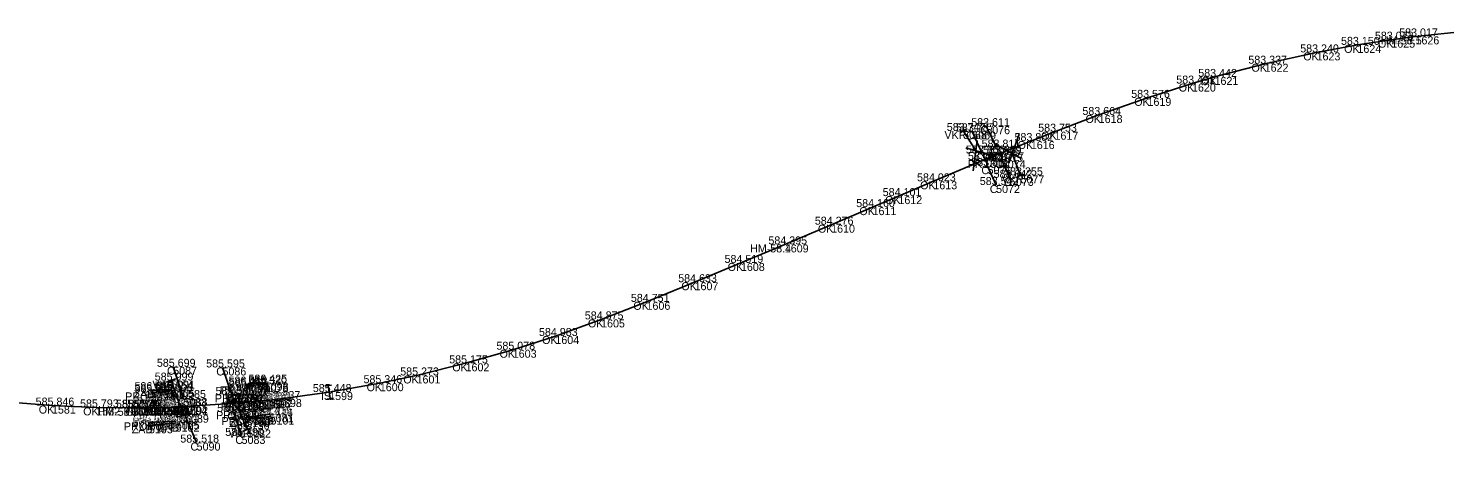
# Model space of a CAD drawing. Extents: x -631472 to -620808, y -1122356 to -1115125.
# Drawn here: x -623680.4 to -623468, y -1119636.8 to -1119573.4 of the extents above; entities that cross this region are included whole.
import ezdxf

# ---------------------------------------------------------------- set-up
doc = ezdxf.new("R2010")
doc.units = 0
for name, color, linetype in [('Vrstva 1', 7, 'Continuous'), ('Vrstva 17', 7, 'Continuous'), ('Vrstva 18', 7, 'Continuous'), ('Vrstva 3', 7, 'Continuous'), ('Vrstva 4', 7, 'Continuous'), ('Vrstva 51', 7, 'Continuous'), ('Vrstva 60', 7, 'Continuous'), ('Vrstva 61', 7, 'Continuous'), ('Vrstva 62', 7, 'Continuous')]:
    doc.layers.add(name, color=color, linetype=linetype)

msp = doc.modelspace()

# ---------------------------------------------------------------- linework, layer by layer
at = {"layer": 'Vrstva 1'}
msp.add_lwpolyline([(-623685.11, -1119629.35), (-623676.9, -1119629.99), (-623670.24, -1119630.26), (-623664.87, -1119630.32), (-623663.9, -1119630.31), (-623663.16, -1119630.3), (-623662.36, -1119630.29), (-623661.98, -1119630.29), (-623661.49, -1119630.28), (-623660.47, -1119630.26), (-623658.91, -1119630.21), (-623658.39, -1119630.19), (-623657.06, -1119630.14), (-623648.54, -1119629.57), (-623647.77, -1119629.5), (-623646.15, -1119629.35), (-623644.69, -1119629.2), (-623644.37, -1119629.16), (-623643, -1119629.01), (-623635.33, -1119627.96), (-623627.73, -1119626.63), (-623622.22, -1119625.47), (-623614.87, -1119623.65), (-623607.79, -1119621.61), (-623601.4, -1119619.55), (-623594.54, -1119617.06), (-623587.73, -1119614.43), (-623580.53, -1119611.48), (-623573.57, -1119608.59), (-623566.99, -1119605.81), (-623560.04, -1119602.85), (-623553.83, -1119600.21), (-623549.95, -1119598.56), (-623544.71, -1119596.34), (-623537.09, -1119593.14), (-623534.83, -1119592.21), (-623530.09, -1119590.3), (-623526.54, -1119588.9), (-623519.91, -1119586.39), (-623512.59, -1119583.82), (-623505.92, -1119581.68), (-623502.54, -1119580.68), (-623495.02, -1119578.7), (-623487.24, -1119577), (-623481.11, -1119575.87), (-623476.03, -1119575.09), (-623472.4, -1119574.6), (-623464.76, -1119573.83)], dxfattribs=at)
at = {"layer": 'Vrstva 17'}
for p, q in [((-623647.98, -1119626.84), (-623644.99, -1119626.55)), ((-623662.07, -1119627.68), (-623659.04, -1119627.58)), ((-623662.35, -1119632.95), (-623658.36, -1119632.7)), ((-623647.75, -1119632.01), (-623644.12, -1119631.64))]:
    msp.add_line(p, q, dxfattribs=at)
at = {"layer": 'Vrstva 18'}
for p, q in [((-623647.9, -1119627.1), (-623645.01, -1119626.8)), ((-623662.07, -1119628.02), (-623659.16, -1119627.88)), ((-623662.28, -1119632.5), (-623658.32, -1119632.37)), ((-623647.63, -1119631.71), (-623644.24, -1119631.28))]:
    msp.add_line(p, q, dxfattribs=at)
at = {"layer": 'Vrstva 3'}
for p, q in [((-623635.96, -1119627.04), (-623634.97, -1119626.91)), ((-623635.69, -1119629.02), (-623634.7, -1119628.89)), ((-623635.47, -1119626.97), (-623635.2, -1119628.95)), ((-623662.01, -1119629.29), (-623661.01, -1119629.27)), ((-623661.51, -1119629.28), (-623661.47, -1119631.28)), ((-623661.97, -1119631.29), (-623660.97, -1119631.27))]:
    msp.add_line(p, q, dxfattribs=at)
at = {"layer": 'Vrstva 4'}
for p, q in [((-623539.83, -1119588.52), (-623540.67, -1119589.06)), ((-623540.25, -1119588.79), (-623538.35, -1119591.73)), ((-623538.13, -1119590.22), (-623538.76, -1119594.79)), ((-623535.58, -1119590.68), (-623531.54, -1119592.9)), ((-623533.41, -1119593.6), (-623531.83, -1119589.27)), ((-623535.4, -1119592.63), (-623539.82, -1119591.31)), ((-623537.09, -1119593.14), (-623534.83, -1119592.21)), ((-623531.64, -1119595.45), (-623532.88, -1119592.17)), ((-623532.11, -1119595.62), (-623531.18, -1119595.27)), ((-623658.3, -1119625.98), (-623659.77, -1119626.5)), ((-623649.65, -1119629.38), (-623649.47, -1119628.92)), ((-623657.28, -1119630.57), (-623657.5, -1119631.01)), ((-623657.06, -1119630.14), (-623648.54, -1119629.57)), ((-623648.34, -1119633.89), (-623646.91, -1119633.29))]:
    msp.add_line(p, q, dxfattribs=at)
for points in [[(-623659.03, -1119626.24), (-623657.87, -1119629.52), (-623656.27, -1119631.08), (-623658.16, -1119631.75), (-623657.87, -1119629.52)], [(-623647.63, -1119633.59), (-623648.99, -1119630.39), (-623650.69, -1119628.94), (-623648.85, -1119628.15), (-623648.99, -1119630.39)]]:
    msp.add_lwpolyline(points, dxfattribs=at)
for centre in [(-623649.56, -1119629.15), (-623657.39, -1119630.79)]:
    msp.add_circle(centre, 0.248, dxfattribs=at)
at = {"layer": 'Vrstva 51'}
for p, q in [((-623535.22, -1119591.28), (-623536.78, -1119588.07)), ((-623537.38, -1119592.18), (-623538.88, -1119588.86)), ((-623535.3, -1119596.9), (-623536.57, -1119594.07)), ((-623533.23, -1119595.82), (-623534.45, -1119593.17)), ((-623657.15, -1119628.85), (-623658.72, -1119624.17)), ((-623649.91, -1119628.39), (-623651.33, -1119624.27)), ((-623648.46, -1119634.54), (-623649.67, -1119630.94)), ((-623655.2, -1119635.54), (-623656.95, -1119631.36))]:
    msp.add_line(p, q, dxfattribs=at)
at = {"layer": 'Vrstva 60'}
for p, q in [((-623476.03, -1119575.09), (-623476.03, -1119575.09)), ((-623472.4, -1119574.6), (-623472.4, -1119574.6)), ((-623487.24, -1119577), (-623487.24, -1119577)), ((-623481.11, -1119575.87), (-623481.11, -1119575.87)), ((-623495.02, -1119578.7), (-623495.02, -1119578.7)), ((-623505.92, -1119581.68), (-623505.92, -1119581.68)), ((-623502.54, -1119580.68), (-623502.54, -1119580.68)), ((-623512.59, -1119583.82), (-623512.59, -1119583.82)), ((-623519.91, -1119586.39), (-623519.91, -1119586.39)), ((-623530.09, -1119590.3), (-623530.09, -1119590.3)), ((-623526.54, -1119588.9), (-623526.54, -1119588.9)), ((-623534.83, -1119592.21), (-623534.83, -1119592.21)), ((-623537.09, -1119593.14), (-623537.09, -1119593.14)), ((-623544.71, -1119596.34), (-623544.71, -1119596.34)), ((-623549.95, -1119598.56), (-623549.95, -1119598.56)), ((-623553.83, -1119600.21), (-623553.83, -1119600.21)), ((-623560.04, -1119602.85), (-623560.04, -1119602.85)), ((-623566.99, -1119605.81), (-623566.99, -1119605.81)), ((-623573.57, -1119608.59), (-623573.57, -1119608.59)), ((-623580.53, -1119611.48), (-623580.53, -1119611.48)), ((-623587.73, -1119614.43), (-623587.73, -1119614.43)), ((-623594.54, -1119617.06), (-623594.54, -1119617.06)), ((-623601.4, -1119619.55), (-623601.4, -1119619.55)), ((-623607.79, -1119621.61), (-623607.79, -1119621.61)), ((-623614.87, -1119623.65), (-623614.87, -1119623.65)), ((-623627.73, -1119626.63), (-623627.73, -1119626.63)), ((-623622.22, -1119625.47), (-623622.22, -1119625.47)), ((-623635.33, -1119627.96), (-623635.33, -1119627.96)), ((-623676.9, -1119629.99), (-623676.9, -1119629.99)), ((-623670.24, -1119630.26), (-623670.24, -1119630.26)), ((-623664.87, -1119630.32), (-623664.87, -1119630.32)), ((-623663.9, -1119630.31), (-623663.9, -1119630.31)), ((-623663.16, -1119630.3), (-623663.16, -1119630.3)), ((-623662.36, -1119630.29), (-623662.36, -1119630.29)), ((-623661.98, -1119630.29), (-623661.98, -1119630.29)), ((-623661.49, -1119630.28), (-623661.49, -1119630.28)), ((-623660.47, -1119630.26), (-623660.47, -1119630.26)), ((-623658.91, -1119630.21), (-623658.91, -1119630.21)), ((-623658.39, -1119630.19), (-623658.39, -1119630.19)), ((-623657.06, -1119630.14), (-623657.06, -1119630.14)), ((-623648.54, -1119629.57), (-623648.54, -1119629.57)), ((-623647.77, -1119629.5), (-623647.77, -1119629.5)), ((-623646.15, -1119629.35), (-623646.15, -1119629.35)), ((-623644.69, -1119629.2), (-623644.69, -1119629.2)), ((-623644.37, -1119629.16), (-623644.37, -1119629.16)), ((-623643, -1119629.01), (-623643, -1119629.01))]:
    msp.add_line(p, q, dxfattribs=at)

# ---------------------------------------------------------------- texts
for s, p in [('1624', (-623481.11, -1119577.07)), ('1625', (-623476.03, -1119576.29)), ('1626', (-623472.4, -1119575.8)), ('1623', (-623487.24, -1119578.2)), ('1622', (-623495.02, -1119579.9)), ('1620', (-623505.92, -1119582.88)), ('1621', (-623502.54, -1119581.88)), ('1619', (-623512.59, -1119585.02)), ('1618', (-623519.91, -1119587.59)), ('5076', (-623536.78, -1119589.27)), ('5068', (-623540.25, -1119589.99)), ('5069', (-623538.88, -1119590.06)), ('1616', (-623530.09, -1119591.5)), ('1617', (-623526.54, -1119590.1)), ('5070', (-623537.38, -1119593.38)), ('5075', (-623535.22, -1119592.48)), ('1615', (-623534.83, -1119593.41)), ('1614', (-623537.09, -1119594.34)), ('5071', (-623536.57, -1119595.27)), ('5074', (-623534.45, -1119594.37)), ('1613', (-623544.71, -1119597.54)), ('5072', (-623535.3, -1119598.1)), ('5073', (-623533.23, -1119597.02)), ('5077', (-623531.64, -1119596.65)), ('1612', (-623549.95, -1119599.76)), ('1611', (-623553.83, -1119601.41)), ('1610', (-623560.04, -1119604.05)), ('1609', (-623566.99, -1119607.01)), ('1608', (-623573.57, -1119609.79)), ('1607', (-623580.53, -1119612.68)), ('1606', (-623587.73, -1119615.62)), ('1605', (-623594.54, -1119618.26)), ('1604', (-623601.4, -1119620.75)), ('1603', (-623607.79, -1119622.81)), ('5087', (-623658.72, -1119625.37)), ('5086', (-623651.33, -1119625.47)), ('1602', (-623614.87, -1119624.85)), ('5091', (-623659.03, -1119627.44)), ('5099', (-623647.98, -1119628.04)), ('5078', (-623645.01, -1119628.01)), ('5098', (-623644.99, -1119627.75)), ('1600', (-623627.73, -1119627.83)), ('1601', (-623622.22, -1119626.67)), ('5104', (-623662.07, -1119628.88)), ('5093', (-623662.07, -1119629.22)), ('5092', (-623659.16, -1119629.08)), ('5105', (-623659.04, -1119628.78)), ('5088', (-623657.15, -1119630.05)), ('5085', (-623649.91, -1119629.59)), ('5097', (-623648.62, -1119629.51)), ('5079', (-623647.9, -1119628.3)), ('1599', (-623635.33, -1119629.16)), ('1581', (-623676.9, -1119631.19)), ('1582', (-623670.24, -1119631.46)), ('1583', (-623664.87, -1119631.52)), ('1584', (-623663.9, -1119631.51)), ('1585', (-623663.16, -1119631.5)), ('1586', (-623662.36, -1119631.49)), ('1587', (-623661.98, -1119631.49)), ('1588', (-623661.49, -1119631.48)), ('1589', (-623660.47, -1119631.46)), ('1590', (-623658.91, -1119631.41)), ('1591', (-623658.39, -1119631.39)), ('1592', (-623657.06, -1119631.34)), ('5084', (-623649.67, -1119632.14)), ('1593', (-623648.54, -1119630.77)), ('5096', (-623648.45, -1119632.03)), ('1594', (-623647.77, -1119630.7)), ('1595', (-623646.15, -1119630.55)), ('1596', (-623644.69, -1119630.4)), ('1597', (-623644.37, -1119630.36)), ('1598', (-623643, -1119630.21)), ('5103', (-623662.35, -1119634.15)), ('5094', (-623662.28, -1119633.7)), ('5102', (-623658.36, -1119633.9)), ('5095', (-623658.32, -1119633.57)), ('5089', (-623656.95, -1119632.56)), ('5100', (-623647.75, -1119633.21)), ('5080', (-623647.63, -1119632.91)), ('5081', (-623644.24, -1119632.48)), ('5101', (-623644.12, -1119632.84)), ('5083', (-623648.46, -1119635.74)), ('5082', (-623647.63, -1119634.79)), ('5090', (-623655.2, -1119636.74))]:
    msp.add_text(s, height=1.2, dxfattribs=at).set_placement(p)
at = {"layer": 'Vrstva 61'}
for s, p in [('583.017', (-623474.85, -1119574.6)), ('583.240', (-623489.69, -1119577)), ('583.150', (-623483.57, -1119575.87)), ('583.073', (-623478.49, -1119575.09)), ('583.337', (-623497.47, -1119578.7)), ('583.442', (-623504.98, -1119580.68)), ('583.491', (-623508.28, -1119581.68)), ('583.576', (-623515.04, -1119583.82)), ('583.664', (-623522.36, -1119586.39)), ('583.747', (-623542.7, -1119588.79)), ('583.787', (-623541.33, -1119588.86)), ('583.611', (-623539.04, -1119588.07)), ('583.753', (-623528.99, -1119588.9)), ('583.811', (-623537.47, -1119591.28)), ('583.802', (-623532.54, -1119590.3)), ('583.856', (-623539.83, -1119592.18)), ('583.902', (-623539.53, -1119593.14)), ('583.812', (-623539.02, -1119594.07)), ('583.869', (-623537.28, -1119592.21)), ('583.777', (-623536.9, -1119593.17)), ('583.642', (-623535.68, -1119595.82)), ('583.255', (-623534.1, -1119595.45)), ('584.023', (-623547.16, -1119596.34)), ('583.542', (-623537.75, -1119596.9)), ('584.160', (-623556.28, -1119600.21)), ('584.101', (-623552.31, -1119598.56)), ('584.276', (-623562.49, -1119602.85)), ('584.395', (-623569.45, -1119605.81)), ('584.519', (-623576.03, -1119608.59)), ('584.633', (-623582.98, -1119611.48)), ('584.751', (-623590.08, -1119614.43)), ('584.875', (-623596.99, -1119617.06)), ('584.983', (-623603.86, -1119619.55)), ('585.078', (-623610.24, -1119621.61)), ('585.175', (-623617.33, -1119623.65)), ('585.699', (-623661.17, -1119624.17)), ('585.595', (-623653.78, -1119624.27)), ('585.273', (-623624.67, -1119625.47)), ('586.615', (-623664.53, -1119627.68)), ('585.504', (-623664.52, -1119628.02)), ('585.606', (-623661.61, -1119627.88)), ('586.554', (-623661.49, -1119627.58)), ('585.999', (-623661.49, -1119626.24)), ('586.416', (-623650.43, -1119626.84)), ('585.367', (-623650.35, -1119627.1)), ('585.320', (-623647.46, -1119626.8)), ('586.425', (-623647.44, -1119626.55)), ('585.448', (-623637.78, -1119627.96)), ('585.346', (-623630.18, -1119626.63)), ('585.846', (-623679.35, -1119629.99)), ('585.585', (-623659.61, -1119628.85)), ('585.683', (-623659.51, -1119630.14)), ('585.565', (-623652.37, -1119628.39)), ('585.576', (-623651.07, -1119628.3)), ('585.592', (-623650.98, -1119629.57)), ('585.583', (-623650.22, -1119629.5)), ('585.567', (-623648.6, -1119629.35)), ('585.554', (-623647.14, -1119629.2)), ('585.551', (-623646.73, -1119629.16)), ('585.537', (-623645.45, -1119629.01)), ('585.793', (-623672.69, -1119630.26)), ('585.754', (-623667.32, -1119630.32)), ('585.746', (-623666.35, -1119630.31)), ('585.740', (-623665.61, -1119630.3)), ('585.732', (-623664.81, -1119630.29)), ('585.728', (-623664.44, -1119630.29)), ('585.724', (-623663.94, -1119630.28)), ('585.716', (-623662.93, -1119630.26)), ('585.701', (-623661.26, -1119630.21)), ('585.695', (-623660.85, -1119630.19)), ('585.794', (-623659.4, -1119631.36)), ('585.663', (-623652.13, -1119630.94)), ('585.706', (-623650.9, -1119630.83)), ('586.486', (-623650.2, -1119632.01)), ('585.508', (-623650.08, -1119631.71)), ('585.415', (-623646.7, -1119631.28)), ('586.446', (-623646.57, -1119631.64)), ('586.800', (-623664.8, -1119632.95)), ('585.612', (-623664.72, -1119632.5)), ('586.823', (-623660.81, -1119632.7)), ('585.621', (-623660.57, -1119632.37)), ('585.736', (-623650.08, -1119633.59)), ('585.518', (-623657.65, -1119635.54)), ('585.490', (-623650.91, -1119634.54))]:
    msp.add_text(s, height=1.2, dxfattribs=at).set_placement(p)
at = {"layer": 'Vrstva 62'}
for s, p in [('OK', (-623483.1, -1119577.07)), ('OK', (-623478.02, -1119576.29)), ('HM-58.5', (-623477.62, -1119575.8)), ('OK', (-623489.23, -1119578.2)), ('OK', (-623497, -1119579.9)), ('OK', (-623507.91, -1119582.88)), ('OK', (-623504.52, -1119581.88)), ('OK', (-623514.58, -1119585.02)), ('OK', (-623521.89, -1119587.59)), ('C', (-623537.72, -1119589.27)), ('VKR', (-623543.05, -1119589.99)), ('C', (-623539.82, -1119590.06)), ('OK', (-623532.07, -1119591.5)), ('OK', (-623528.53, -1119590.1)), ('C', (-623538.31, -1119593.38)), ('PRJ', (-623537.32, -1119593.41)), ('C', (-623536.16, -1119592.48)), ('PRJ', (-623539.57, -1119594.34)), ('C', (-623537.51, -1119595.27)), ('C', (-623535.38, -1119594.37)), ('OK', (-623546.69, -1119597.54)), ('C', (-623536.24, -1119598.1)), ('VKR', (-623534.45, -1119596.65)), ('C', (-623534.16, -1119597.02)), ('OK', (-623551.94, -1119599.76)), ('OK', (-623555.81, -1119601.41)), ('OK', (-623562.02, -1119604.05)), ('HM-58.4', (-623572.2, -1119607.01)), ('OK', (-623575.56, -1119609.79)), ('OK', (-623582.51, -1119612.68)), ('OK', (-623589.71, -1119615.62)), ('OK', (-623596.52, -1119618.26)), ('OK', (-623603.39, -1119620.75)), ('OK', (-623609.77, -1119622.81)), ('C', (-623659.65, -1119625.37)), ('C', (-623652.26, -1119625.47)), ('OK', (-623616.86, -1119624.85)), ('VKR', (-623661.84, -1119627.44)), ('PROP', (-623648.84, -1119628.01)), ('ZAB', (-623647.59, -1119627.75)), ('OK', (-623629.71, -1119627.83)), ('OK', (-623624.21, -1119626.67)), ('PROP', (-623665.91, -1119629.22)), ('ZAB', (-623664.67, -1119628.88)), ('PROP', (-623663, -1119629.08)), ('ZAB', (-623661.64, -1119628.78)), ('C', (-623658.09, -1119630.05)), ('PROP', (-623652.46, -1119629.51)), ('PROP', (-623651.73, -1119628.3)), ('C', (-623650.85, -1119629.59)), ('ZAB', (-623650.58, -1119628.04)), ('IS', (-623636.56, -1119629.16)), ('OK', (-623678.88, -1119631.19)), ('OK', (-623672.22, -1119631.46)), ('HM-58.3', (-623670.07, -1119631.52)), ('PROP', (-623666.2, -1119631.49)), ('OK', (-623665.88, -1119631.51)), ('PROP', (-623665.82, -1119631.49)), ('OK', (-623665.14, -1119631.5)), ('PROP', (-623664.31, -1119631.46)), ('IS', (-623662.72, -1119631.48)), ('PROP', (-623662.22, -1119631.39)), ('OK', (-623660.89, -1119631.41)), ('PRJ', (-623659.54, -1119631.34)), ('PROP', (-623652.28, -1119632.03)), ('PROP', (-623651.6, -1119630.7)), ('PRJ', (-623651.02, -1119630.77)), ('C', (-623650.61, -1119632.14)), ('PROP', (-623649.99, -1119630.55)), ('PROP', (-623648.53, -1119630.4)), ('PROP', (-623648.21, -1119630.36)), ('OK', (-623644.98, -1119630.21)), ('PROP', (-623666.11, -1119633.7)), ('ZAB', (-623664.95, -1119634.15)), ('PROP', (-623662.15, -1119633.57)), ('ZAB', (-623660.96, -1119633.9)), ('C', (-623657.88, -1119632.56)), ('PROP', (-623651.46, -1119632.91)), ('ZAB', (-623650.35, -1119633.21)), ('PROP', (-623648.07, -1119632.48)), ('ZAB', (-623646.72, -1119632.84)), ('VKR', (-623650.43, -1119634.79)), ('C', (-623649.4, -1119635.74)), ('C', (-623656.13, -1119636.74))]:
    msp.add_text(s, height=1.2, dxfattribs=at).set_placement(p)

doc.saveas('drawing.dxf')
